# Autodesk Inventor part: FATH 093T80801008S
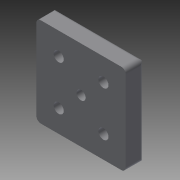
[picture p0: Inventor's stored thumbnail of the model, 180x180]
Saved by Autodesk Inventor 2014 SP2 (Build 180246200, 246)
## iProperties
Created: 2018-10
Part Number: FATH 093T80801008S
Material: Generic
Catalog Web Link: www.cadenas.de
Description: Transport and Base Plate 80 x 80-Die-cast Zinc
Vendor: FATH
Document SubType Name: Modeling
Designer: psadmin
Manufacturer: FATH
Mass: 92.6068 g
Surface Area: 196.714 cm^2
Volume: 92.6068 cm^3
Density: 1 g/cm^3
Appearance: PSOLRGB-175-175-175
Category: PARTsolutions
Company: FATH
Title: FATH 093T80801008S
Author: Cadenas PARTsolutions
Comments: Die-cast Zinc
PSOL_IDENT_0: {$CADENAS_DATA\23d-libs\fath\zubehoer_alu_sys\fussplatten\093t8080.prj},194 {VTYP=3D},{NB=FATH 093T8
PSOL_IDENT_1: 0801008S},{LINA=FATH 093T80801008S},{NN=Transport and Base Plate 80 x 80},{DATE=19.02.2018 15:31:06}
PSOL_IDENT_2: ,{GEOMDATE=26.05.2005},{VERSION=},{LINEID=740},{WBVAR=},{WBNUMERIC=}  {NB=FATH 093T80801008S},{LINA=
PSOL_IDENT_3: FATH 093T80801008S},{KT=DUMMY},{BO=für M8},{D=9.0},{DIM=80x80},{A=40},{M=M10},{O=pulverbeschichtet},
PSOL_IDENT_4: {ARTNR=093T80801008S},{PRTNO=},{L=80},{B=80},{H=16},{D1=9.0},{D2=15},{T=9.0},{GEW=10},{KD=8.2},{R1=4
PSOL_IDENT_5: .0},{R2=3},{FO=2}
NN: Transport- und Fußplatte 80x80
NT: Zinkdruckguss
NB: FATH 093T80801008S
NBSYN: FATH $ARTNR.
LINA: FATH 093T80801008S
BO: für M8
D: 9
DIM: 80x80
A: 40
M: M10
O: pulverbeschichtet
ARTNR: 093T80801008S
SUPPLIER: FATH
ARTICLENO: FATH 093T80801008S
BOMINFO: FATH 093T80801008S
CREATOR: CADENAS GmbH
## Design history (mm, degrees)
sketch "Skizze_1"
  geometry: L1 (36, 40)-(-36, 40); L2 (-40, 36)-(-40, -36); L3 (-36, -40)-(36, -40); L4 (40, -36)-(40, 36); A1 r 4 centre (36, 36) between (40, 36) and (36, 40); A2 r 4 centre (-36, 36) between (-36, 40) and (-40, 36); A3 r 4 centre (-36, -36) between (-40, -36) and (-36, -40); A4 r 4 centre (36, -36) between (36, -40) and (40, -36)
  constraints: 8 end point, 8 point on circle, 4 centre point
extrude "Extrusion1" join sketch "Skizze_1" distance "d0" = 16; taper "d1" = 0 deg
sketch "Skizze_2"
  geometry: L1 (19, 43)-(0, 43); L2 (0, 43)-(0, 40); L3 (0, 40)-(13, 40); L4 (16, 37)-(16, -37); L5 (13, -40)-(0, -40); L6 (0, -40)-(0, -43); L7 (0, -43)-(19, -43); L8 (19, -43)-(19, 43); A1 r 3 centre (13, 37) between (16, 37) and (13, 40); A2 r 3 centre (13, -37) between (13, -40) and (16, -37)
  constraints: 16 end point, 4 point on circle, 2 centre point
extrude "Extrusion2" cut sketch "Skizze_2" stored distance "d2" = 80; taper "d3" = 0 deg
sketch "Skizze_3"
  geometry: L1 (-43, 19)-(-43, 0); L2 (-43, 0)-(-40, 0); L3 (-40, 0)-(-40, 13); L4 (-37, 16)-(37, 16); L5 (40, 13)-(40, 0); L6 (40, 0)-(43, 0); L7 (43, 0)-(43, 19); L8 (43, 19)-(-43, 19); A1 r 3 centre (-37, 13) between (-37, 16) and (-40, 13); A2 r 3 centre (37, 13) between (40, 13) and (37, 16)
  constraints: 16 end point, 4 point on circle, 2 centre point
extrude "Extrusion3" cut sketch "Skizze_3" stored distance "d4" = 80; taper "d5" = 0 deg
sketch "Skizze_7"
  geometry: L1 (-20, 18)-(-20, 0); L2 (-20, 0)-(-24.5, 0); L3 (-24.5, 0)-(-24.5, 7); L4 (-24.5, 7)-(-27.5, 7); L5 (-27.5, 7)-(-27.5, 18); L6 (-27.5, 18)-(-20, 18); L7 (-20, 18)-(-20, 0)
  constraints: 14 end point
revolve "Revolution1" sketch "Skizze_7" stored, may be unused: angle "d6" = 360 deg
sketch "Skizze_8"
  geometry: L1 (20, 18)-(20, 0); L2 (20, 0)-(15.5, 0); L3 (15.5, 0)-(15.5, 7); L4 (15.5, 7)-(12.5, 7); L5 (12.5, 7)-(12.5, 18); L6 (12.5, 18)-(20, 18); L7 (20, 18)-(20, 0)
  constraints: 14 end point
revolve "Revolution2" sketch "Skizze_8" stored, may be unused: angle "d7" = 360 deg
sketch "Skizze_9"
  geometry: L1 (-20, 18)-(-20, 0); L2 (-20, 0)-(-24.5, 0); L3 (-24.5, 0)-(-24.5, 7); L4 (-24.5, 7)-(-27.5, 7); L5 (-27.5, 7)-(-27.5, 18); L6 (-27.5, 18)-(-20, 18); L7 (-20, 18)-(-20, 0)
  constraints: 14 end point
revolve "Revolution3" sketch "Skizze_9" stored, may be unused: angle "d8" = 360 deg
sketch "Skizze_10"
  geometry: L1 (20, 18)-(20, 0); L2 (20, 0)-(15.5, 0); L3 (15.5, 0)-(15.5, 7); L4 (15.5, 7)-(12.5, 7); L5 (12.5, 7)-(12.5, 18); L6 (12.5, 18)-(20, 18); L7 (20, 18)-(20, 0)
  constraints: 14 end point
revolve "Revolution4" sketch "Skizze_10" stored, may be unused: angle "d9" = 360 deg
sketch "Sketch8"
  geometry: 1 further point
hole "Hole1" sketch "Sketch8" at (0, 0) diameter "d10" = 8.2; stored, may be unused: countersink angle "d14" = 90 deg, drill point angle "d16" = 0 deg; dims "d11" = 6, "d12" = 4, "d13" = 2, "d15" = 16
body "Solid1"
